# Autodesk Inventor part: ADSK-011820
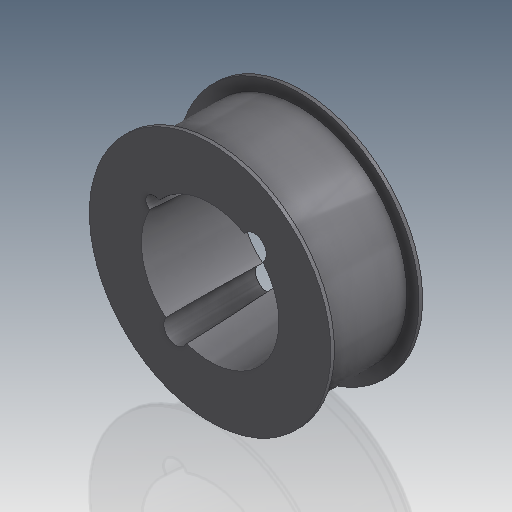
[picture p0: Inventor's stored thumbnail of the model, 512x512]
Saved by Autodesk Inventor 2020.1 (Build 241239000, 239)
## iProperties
Created: 1999-11
Part Number: ADSK-011820
Description: SPROCKET,TIMING,8MMX36T,1610BUSH
Document SubType Name: Modeling
Designer: mpflueger
Material: Acier doux
Density: 7.86 g/cm^3
Appearance: Metal-Steel(Polish)
Mass: 1202.37 g
Surface Area: 321.775 cm^2
Volume: 152.973 cm^3
Control State: 0
Master: False
Checked Out: False
Shininess: 60.0
Length Units: 11269
Angle Units: 11279
Time Units: 11290
Mass Units: 11283
Length Display Precision: 3
Angle Display Precision: 2
Compacted: True
Dimensions: 100x38x100 mm
Mass: 1,202 kg
VLT_Material: Acier doux
DocNumber: ADSK-011820.ipt
Folder: 01 - Themengebiete\Simplification\01 - Packaging machine\
VDS_Category: 3D Komponenten
Density: 7.86
Volumn: 131.38854252371846
Area: 299.6185747203996
PropertySet Name: Model Information
Author: mpflueger
Revision Number: -
Title: SPROCKET,TIMING,8MMX36T,1610BUSH
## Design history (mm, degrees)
node "Solide1"
  node "Extrusion1" dims "d0" = 38, "d1" = 0
  node "Extrusion3" dims "d8" = 1.5, "d9" = 0
  node "Extrusion4" dims "d10" = 1.5, "d11" = 0
sketch "Sketch3"
  geometry: C1 r 45 at (0, 0) reference; C2 r 50 at (0, 0)
  constraints: 1 centre point, 1 coincident
  dimensions: "d7" = 99.9998 diameter of C2
sketch "Skizze6"
  geometry: L1 (0, 0)-(0, 28.5); L2 (0, 0)-(18.319, 21.832); L3 (0, 0)-(-14.25, -24.682); L4 (0, 0)-(-23.346, 16.347); A1 r 28.5 centre (0, 0) between (0, 28.5) and (18.319, 21.832); 3 further points
  constraints: 8 end point, 4 point on circle, 3 coincident, 1 centre point, 1 vertical
  dimensions: "d15" = 57 diameter of A1; "d16" = 40 deg angle of L1 L2; "d17" = 170 deg angle of L3 L2; "d26" = 55 deg angle of L1 L4
hole "Bohrung2" sketch "Skizze6" at (-23.346, 16.347) diameter "d27" = 6.6; stored, may be unused: countersink angle "d31" = 90 deg, drill point angle "d33" = 118 deg; dims "d28" = 6, "d29" = 4, "d30" = 2, "d32" = 8
workplane "Arbeitsebene1"
sketch "Sketch4"
  geometry: C1 r 45 at (0, 0) reference; C2 r 50 at (0, 0) reference
feature "FaceDraft1" dims angle "d14" = -4 deg
hole "Bohrung1" sketch "Skizze6" diameter "d18" = 10; stored, may be unused: countersink angle "d22" = 90 deg, drill point angle "d24" = 118 deg; dims "d19" = 6, "d20" = 4, "d21" = 2, "d23" = 8
node "Corps solides"
node "Corps surfaciques"
sketch "Sketch1"
  geometry: C1 r 28.5 at (0, 0); C2 r 45 at (0, 0)
  constraints: 2 centre point, 1 coincident
  dimensions: "d2" = 57 diameter of C1; "d3" = 90 diameter of C2
